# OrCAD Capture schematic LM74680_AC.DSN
size Custom; title: TPS54233 :2A, 28V INPUT, STEP DOWN SWIFT; rev: 1.0; note: SNOSDF8 – DEC 2024
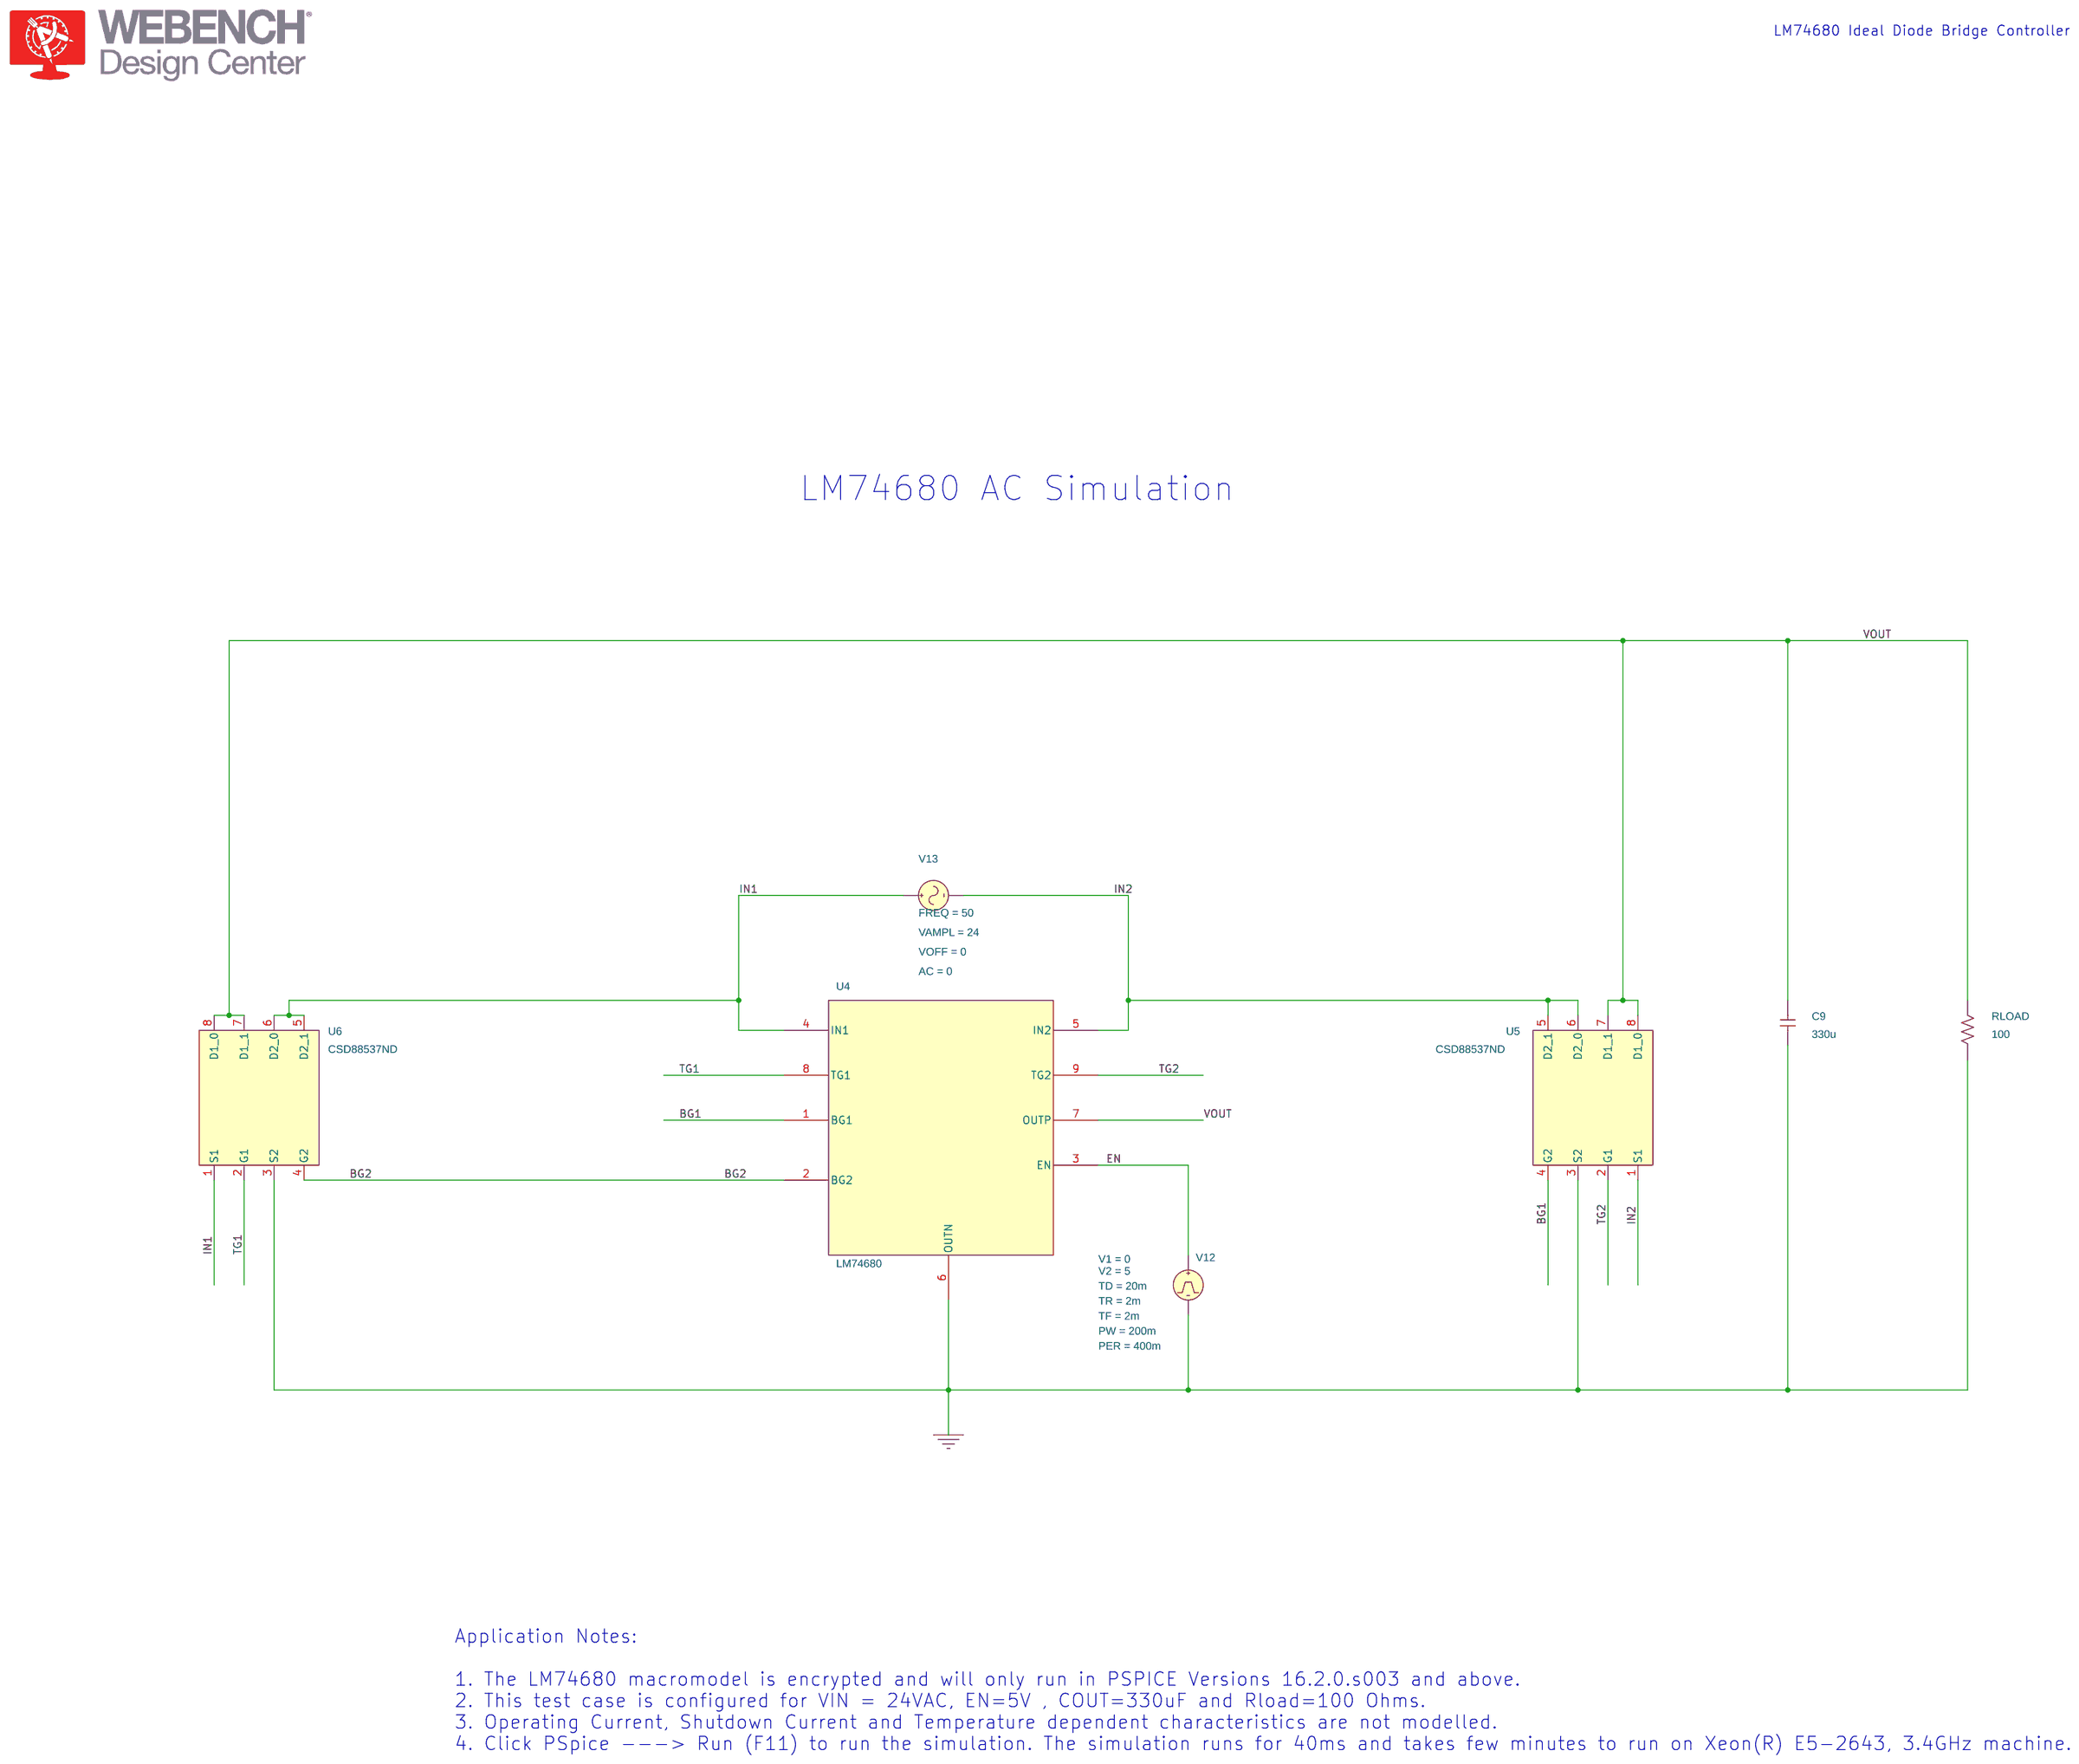
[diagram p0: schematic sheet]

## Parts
C9  330u  [RAD/CK05]
RLOAD  100  [AX/RC05]
U4  LM74680
U5  CSD88537ND
U6  CSD88537ND
V12  VPULSE
V13  VSIN

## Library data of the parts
C9 = C
RLOAD = R
U4 = LM74680
U5 U6 = CSD88537ND
V12 = VPULSE: PER: 400m; PW: 200m; TD: 20m; TF: 2m; TR: 2m; V1: 0; V2: 5
V13 = VSIN: AC: 0; FREQ: 50; VAMPL: 24; VOFF: 0

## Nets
0: C9.1 RLOAD.1 U4.6(OUTN) U5.3(S2) U6.3(S2) V12.2(-)
BG1: U4.1(BG1) U5.4(G2)
BG2: U4.2(BG2) U6.4(G2)
EN: U4.3(EN) V12.1(+)
IN1: U4.4(IN1) U6.1(S1) U6.5(D2_1) U6.6(D2_0) V13.1(+)
IN2: U4.5(IN2) U5.1(S1) U5.5(D2_1) U5.6(D2_0) V13.2(-)
TG1: U4.8(TG1) U6.2(G1)
TG2: U4.9(TG2) U5.2(G1)
VOUT: C9.2 RLOAD.2 U4.7(OUTP) U5.7(D1_1) U5.8(D1_0) U6.7(D1_1) U6.8(D1_0)

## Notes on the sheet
- LM74680 Ideal Diode Bridge Controller
- LM74680 AC Simulation
- Application Notes:
  1. The LM74680 macromodel is encrypted and will only run in PSPICE Versions 16.2.0.s003 and above.
  2. This test case is configured for VIN = 24VAC, EN=5V , COUT=330uF and Rload=100 Ohms.
  3. Operating Current, Shutdown Current and Temperature dependent characteristics are not modelled.
  4. Click PSpice ---> Run (F11) to run the simulation. The simulation runs for 40ms and takes few minutes to run on Xeon(R) E5-2643, 3.4GHz machine.
